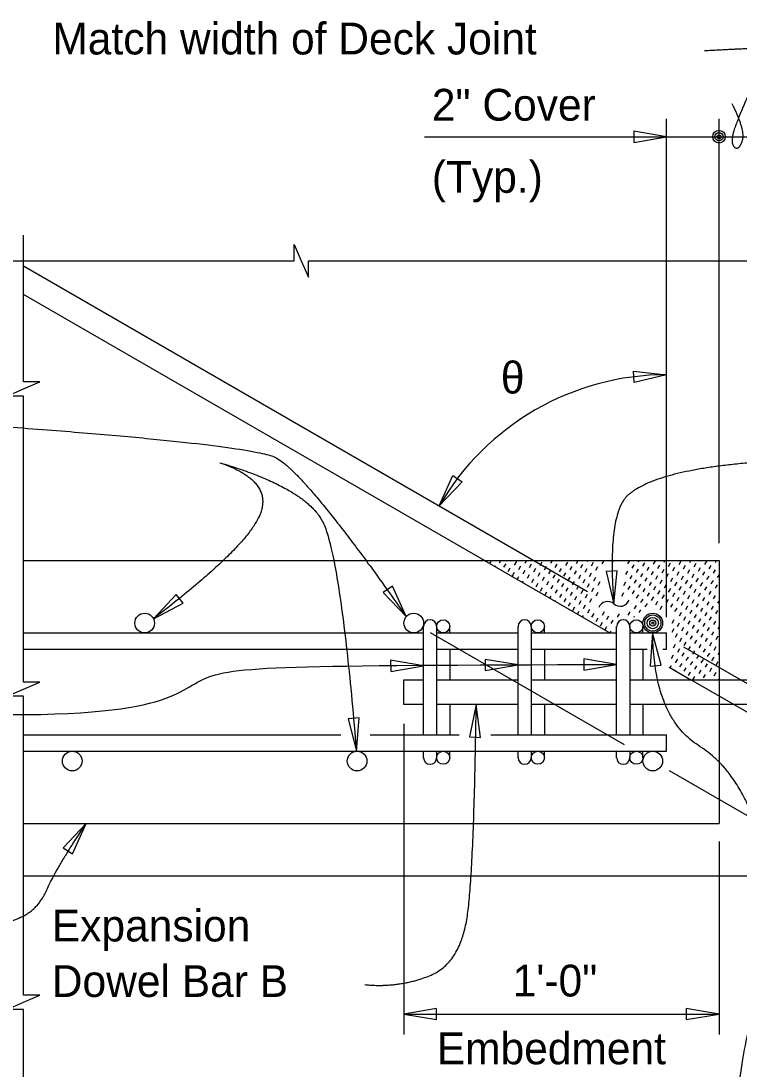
# Model space of a CAD drawing. Extents: x 0 to 20.5, y 0 to 13.
# Drawn here: x 3.293 to 5.57, y 2.072 to 5.395 of the extents above; entities that cross this region are included whole.
import ezdxf

# ---------------------------------------------------------------- set-up
doc = ezdxf.new("R2010")
doc.units = 0
for name, color, linetype in [('Dimension', 7, 'Continuous'), ('Miscellaneous', 7, 'Continuous'), ('Rebar', 7, 'Continuous'), ('TextStructures', 7, 'Continuous'), ('TrafBarrierConc', 7, 'Continuous')]:
    doc.layers.add(name, color=color, linetype=linetype)

msp = doc.modelspace()

# ---------------------------------------------------------------- linework, layer by layer
at = {"layer": 'Dimension'}
for p, q in [((5.3402, 3.5042), (5.3402, 5.0841)), ((5.5069, 3.7386), (5.5069, 5.0841)), ((4.5726, 5.0275), (6.6325, 5.0275)), ((4.5904, 3.456), (5.2064, 3.1004)), ((4.507, 3.1659), (4.507, 2.1806)), ((5.3491, 3.018), (6.7489, 2.2099)), ((5.5069, 2.7927), (5.5069, 2.1806)), ((4.507, 2.2457), (5.5069, 2.2457))]:
    msp.add_line(p, q, dxfattribs=at)
for points in [[(5.3402, 5.0275), (5.2361, 5.0452), (5.2361, 5.0099)], [(5.2352, 4.2842), (5.3402, 4.2732), (5.2375, 4.249)], [(4.6922, 3.9338), (4.6196, 3.8571), (4.6629, 3.9535)], [(5.1731, 3.5466), (5.184, 3.6517), (5.1488, 3.6494)], [(4.5151, 3.506), (4.4714, 3.6022), (4.4422, 3.5824)], [(3.7135, 3.4995), (3.8071, 3.5486), (3.7857, 3.5767)], [(5.2962, 3.4545), (5.2886, 3.3491), (5.3237, 3.3525)], [(4.5697, 3.3505), (4.4655, 3.3677), (4.4657, 3.3325)], [(4.8696, 3.3531), (4.7654, 3.3703), (4.7656, 3.335)], [(5.1821, 3.3548), (5.0779, 3.372), (5.0781, 3.3367)], [(4.7368, 3.2279), (4.715, 3.1245), (4.7503, 3.1231)], [(4.3568, 3.0795), (4.3658, 3.1848), (4.3307, 3.1819)], [(3.4996, 2.8503), (3.4275, 2.7731), (3.457, 2.7537)], [(4.507, 2.2457), (4.6111, 2.2281), (4.6111, 2.2634)], [(5.5069, 2.2457), (5.4028, 2.2634), (5.4028, 2.2281)]]:
    msp.add_lwpolyline(points, close=True, dxfattribs=at)
for points in [[(3.2111, 4.6346), (4.1595, 4.6346), (4.1595, 4.6863), (4.182, 4.6346), (4.2045, 4.583), (4.2045, 4.6346), (5.6705, 4.6346)], [(3.3015, 3.7833), (3.3015, 4.2056), (3.2499, 4.2056), (3.3015, 4.2281), (3.3532, 4.2506), (3.3015, 4.2506), (3.3015, 4.7161)], [(3.3015, 2.5222), (3.3015, 3.2538), (3.2499, 3.2538), (3.3015, 3.2763), (3.3532, 3.2988), (3.3015, 3.2988), (3.3015, 3.7833)], [(3.3015, 1.1553), (3.3015, 2.2607), (3.2499, 2.2607), (3.3015, 2.2832), (3.3532, 2.3057), (3.3015, 2.3057), (3.3015, 2.5222)]]:
    msp.add_lwpolyline(points, dxfattribs=at)
for radius in [0.0199, 0.0131, 0.00592]:
    msp.add_circle((5.5067, 5.0278), radius, dxfattribs=at)
for centre, radius, start, end in [((5.3402, 3.4411), 0.8321, 90, 150.0024), ((5.1934, 3.5687), 0.0298, 227.8396, 339.5668), ((5.1534, 3.5245), 0.0298, 47.8396, 159.5668)]:
    msp.add_arc(centre, radius, start, end, dxfattribs=at)
for points, degree in [([(5.4604, 5.301), (5.5667, 5.3067), (5.6696, 5.3108), (5.5594, 5.0732), (5.5432, 5.0015), (5.5714, 4.9852), (5.5909, 5.0482), (5.5486, 5.1318)], 2), ([(2.9729, 4.1274), (4.0086, 4.0579), (4.195, 3.962), (4.5151, 3.506)], 2), ([(3.9235, 3.9942), (4.0937, 3.9366), (4.0091, 3.7247), (3.7135, 3.4995)], 2), ([(3.9235, 3.9942), (4.1911, 3.9157), (4.3056, 3.7037), (4.3568, 3.0795)], 2), ([(6.0258, 4.0142), (5.6594, 4.0068), (5.2857, 3.9502), (5.1513, 3.8332), (5.173, 3.5466)], 2), ([(5.6346, 2.3146), (5.7045, 2.5366), (5.5862, 3.0064), (5.2999, 3.1865), (5.2963, 3.4545)], 2), ([(3.0126, 3.2007), (3.7468, 3.1725), (3.8032, 3.3526), (4.1263, 3.3505), (5.1821, 3.3548)], 3), ([(4.3833, 2.3391), (4.4944, 2.3283), (4.6907, 2.4097), (4.7303, 2.7298), (4.7368, 3.2279)], 2), ([(5.2452, 1.4729), (5.5852, 1.5133), (5.5498, 1.8019), (5.596, 2.2664), (5.8349, 3.0174)], 2), ([(3.0522, 2.528), (3.1574, 2.528), (3.2363, 2.528), (3.3481, 2.5773), (3.402, 2.7023), (3.4996, 2.8503)], 2)]:
    msp.add_open_spline(points, degree=degree, dxfattribs=at)
at = {"layer": 'Miscellaneous'}
for p, q in [((4.7798, 3.6743), (4.7838, 3.6812)), ((4.796, 3.665), (4.7975, 3.6675)), ((4.8111, 3.6765), (4.8153, 3.6836)), ((4.8248, 3.6628), (4.8313, 3.674)), ((4.8384, 3.6491), (4.8449, 3.6603)), ((4.8449, 3.6829), (4.8453, 3.6836)), ((4.8586, 3.6693), (4.8651, 3.6805)), ((4.8723, 3.6556), (4.8787, 3.6668)), ((4.8924, 3.6758), (4.897, 3.6836)), ((4.9061, 3.6621), (4.9125, 3.6733)), ((4.9197, 3.6484), (4.9262, 3.6596)), ((4.9262, 3.6822), (4.927, 3.6836)), ((4.9399, 3.6686), (4.9464, 3.6798)), ((4.9535, 3.6549), (4.96, 3.6661)), ((4.9737, 3.6751), (4.9786, 3.6836)), ((4.9873, 3.6614), (4.9938, 3.6726)), ((5.001, 3.6477), (5.0075, 3.6589)), ((5.0075, 3.6815), (5.0087, 3.6836)), ((5.0212, 3.6679), (5.0276, 3.6791)), ((5.0348, 3.6542), (5.0413, 3.6654)), ((5.055, 3.6744), (5.0603, 3.6836)), ((5.0686, 3.6607), (5.0751, 3.6719)), ((5.0823, 3.647), (5.0888, 3.6582)), ((5.0888, 3.6808), (5.0904, 3.6836)), ((5.1024, 3.6672), (5.1089, 3.6784)), ((5.1161, 3.6535), (5.1226, 3.6647)), ((5.1362, 3.6737), (5.142, 3.6836)), ((5.17, 3.6801), (5.1721, 3.6836)), ((5.2175, 3.673), (5.2237, 3.6836)), ((5.2312, 3.6593), (5.2377, 3.6705)), ((5.2448, 3.6456), (5.2513, 3.6568)), ((5.2513, 3.6794), (5.2538, 3.6836)), ((5.265, 3.6658), (5.2715, 3.677)), ((5.2787, 3.6521), (5.2851, 3.6633)), ((5.2988, 3.6723), (5.3053, 3.6835)), ((5.3125, 3.6586), (5.3189, 3.6698)), ((5.3261, 3.6449), (5.3326, 3.6561)), ((5.3326, 3.6787), (5.3354, 3.6836)), ((5.3463, 3.6651), (5.3528, 3.6763)), ((5.3599, 3.6514), (5.3664, 3.6626)), ((5.3801, 3.6716), (5.3866, 3.6828)), ((5.3937, 3.6579), (5.4002, 3.6691)), ((5.4139, 3.678), (5.4171, 3.6836)), ((5.4276, 3.6644), (5.434, 3.6756)), ((5.4412, 3.6507), (5.4477, 3.6619)), ((5.4614, 3.6709), (5.4678, 3.6821)), ((5.475, 3.6572), (5.4815, 3.6684)), ((5.4952, 3.6773), (5.4988, 3.6836)), ((4.8521, 3.6355), (4.8586, 3.6467)), ((4.867, 3.624), (4.8723, 3.633)), ((4.8859, 3.642), (4.8924, 3.6531)), ((4.8996, 3.6283), (4.9061, 3.6395)), ((4.9132, 3.6146), (4.9197, 3.6258)), ((4.9334, 3.6348), (4.9399, 3.646)), ((4.9471, 3.6211), (4.9535, 3.6323)), ((4.9672, 3.6413), (4.9737, 3.6524)), ((4.9809, 3.6276), (4.9873, 3.6388)), ((4.9945, 3.6139), (5.001, 3.6251)), ((5.0147, 3.6341), (5.0212, 3.6453)), ((5.0283, 3.6204), (5.0348, 3.6316)), ((5.0485, 3.6406), (5.055, 3.6517)), ((5.0621, 3.6269), (5.0686, 3.6381)), ((5.0758, 3.6132), (5.0823, 3.6244)), ((5.0959, 3.6334), (5.1024, 3.6446)), ((5.1096, 3.6197), (5.1161, 3.6309)), ((5.211, 3.6392), (5.2175, 3.6503)), ((5.2247, 3.6255), (5.2312, 3.6367)), ((5.2384, 3.6118), (5.2448, 3.623)), ((5.2585, 3.632), (5.265, 3.6432)), ((5.2722, 3.6183), (5.2787, 3.6295)), ((5.2923, 3.6385), (5.2988, 3.6496)), ((5.306, 3.6248), (5.3125, 3.636)), ((5.3398, 3.6313), (5.3463, 3.6425)), ((5.3535, 3.6176), (5.3599, 3.6288)), ((5.3736, 3.6378), (5.3801, 3.6489)), ((5.3873, 3.6241), (5.3937, 3.6353)), ((5.4074, 3.6442), (5.4139, 3.6554)), ((5.4211, 3.6306), (5.4276, 3.6418)), ((5.4347, 3.6169), (5.4412, 3.6281)), ((5.4549, 3.6371), (5.4614, 3.6482)), ((5.4685, 3.6234), (5.475, 3.6346)), ((5.4887, 3.6435), (5.4952, 3.6547)), ((5.5024, 3.6299), (5.5069, 3.6377)), ((4.8832, 3.6146), (4.8859, 3.6193)), ((4.8994, 3.6053), (4.8996, 3.6057)), ((4.9269, 3.601), (4.9334, 3.6122)), ((4.9406, 3.5873), (4.9471, 3.5985)), ((4.9607, 3.6074), (4.9672, 3.6186)), ((4.9744, 3.5938), (4.9809, 3.605)), ((4.988, 3.5801), (4.9945, 3.5913)), ((5.0082, 3.6003), (5.0147, 3.6115)), ((5.0219, 3.5866), (5.0283, 3.5978)), ((5.042, 3.6067), (5.0485, 3.6179)), ((5.0557, 3.5931), (5.0621, 3.6043)), ((5.0693, 3.5794), (5.0758, 3.5906)), ((5.0895, 3.5996), (5.0959, 3.6108)), ((5.1031, 3.5859), (5.1096, 3.5971)), ((5.1233, 3.606), (5.1298, 3.6172)), ((5.2046, 3.6053), (5.211, 3.6165)), ((5.2182, 3.5917), (5.2247, 3.6029)), ((5.252, 3.5982), (5.2585, 3.6094)), ((5.2657, 3.5845), (5.2722, 3.5957)), ((5.2858, 3.6046), (5.2923, 3.6158)), ((5.2995, 3.591), (5.306, 3.6022)), ((5.3196, 3.6111), (5.3261, 3.6223)), ((5.3333, 3.5975), (5.3398, 3.6087)), ((5.347, 3.5838), (5.3535, 3.595)), ((5.3671, 3.6039), (5.3736, 3.6151)), ((5.3808, 3.5903), (5.3873, 3.6015)), ((5.4009, 3.6104), (5.4074, 3.6216)), ((5.4146, 3.5968), (5.4211, 3.608)), ((5.4283, 3.5831), (5.4347, 3.5943)), ((5.4484, 3.6032), (5.4549, 3.6144)), ((5.4621, 3.5896), (5.4685, 3.6008)), ((5.4822, 3.6097), (5.4887, 3.6209)), ((5.4959, 3.5961), (5.5024, 3.6073)), ((4.9542, 3.5736), (4.9607, 3.5848)), ((4.9704, 3.5643), (4.9744, 3.5712)), ((4.9866, 3.555), (4.988, 3.5575)), ((5.0017, 3.5665), (5.0082, 3.5776)), ((5.0154, 3.5528), (5.0219, 3.564)), ((5.0355, 3.5729), (5.042, 3.5841)), ((5.0492, 3.5593), (5.0557, 3.5705)), ((5.0628, 3.5456), (5.0693, 3.5568)), ((5.083, 3.5658), (5.0895, 3.5769)), ((5.0966, 3.5521), (5.1031, 3.5633)), ((5.1168, 3.5722), (5.1233, 3.5834)), ((5.1981, 3.5715), (5.2046, 3.5827)), ((5.2319, 3.578), (5.2384, 3.5892)), ((5.2455, 3.5644), (5.252, 3.5755)), ((5.2592, 3.5507), (5.2657, 3.5619)), ((5.2794, 3.5708), (5.2858, 3.582)), ((5.293, 3.5572), (5.2995, 3.5684)), ((5.3132, 3.5773), (5.3196, 3.5885)), ((5.3268, 3.5637), (5.3333, 3.5748)), ((5.3405, 3.55), (5.347, 3.5612)), ((5.3606, 3.5701), (5.3671, 3.5813)), ((5.3743, 3.5565), (5.3808, 3.5677)), ((5.3944, 3.5766), (5.4009, 3.5878)), ((5.4081, 3.563), (5.4146, 3.5741)), ((5.4218, 3.5493), (5.4283, 3.5605)), ((5.4419, 3.5694), (5.4484, 3.5806)), ((5.4556, 3.5558), (5.4621, 3.567)), ((5.4757, 3.5759), (5.4822, 3.5871)), ((5.4894, 3.5623), (5.4959, 3.5734)), ((5.029, 3.5391), (5.0355, 3.5503)), ((5.0427, 3.5255), (5.0492, 3.5367)), ((5.0576, 3.5139), (5.0628, 3.523)), ((5.0765, 3.5319), (5.083, 3.5431)), ((5.0902, 3.5183), (5.0966, 3.5295)), ((5.2391, 3.5305), (5.2455, 3.5417)), ((5.2539, 3.519), (5.2592, 3.5281)), ((5.2729, 3.537), (5.2794, 3.5482)), ((5.3067, 3.5435), (5.3132, 3.5547)), ((5.3196, 3.5292), (5.3261, 3.5404)), ((5.3534, 3.5357), (5.3599, 3.5469)), ((5.3671, 3.5221), (5.3735, 3.5332)), ((5.388, 3.5428), (5.3944, 3.554)), ((5.4016, 3.5291), (5.4081, 3.5403)), ((5.4153, 3.5155), (5.4218, 3.5267)), ((5.4354, 3.5356), (5.4419, 3.5468)), ((5.4491, 3.522), (5.4556, 3.5332)), ((5.4692, 3.5421), (5.4757, 3.5533)), ((5.4829, 3.5284), (5.4894, 3.5396)), ((5.4966, 3.5148), (5.5031, 3.526)), ((5.5031, 3.5486), (5.5069, 3.5553)), ((5.0738, 3.5046), (5.0765, 3.5093)), ((5.0899, 3.4953), (5.0902, 3.4957)), ((5.1038, 3.5046), (5.1103, 3.5158)), ((5.1175, 3.491), (5.124, 3.5021)), ((5.1376, 3.5111), (5.1441, 3.5223)), ((5.1513, 3.4974), (5.1578, 3.5086)), ((5.165, 3.4838), (5.1714, 3.495)), ((5.1851, 3.5039), (5.1916, 3.5151)), ((5.2189, 3.5104), (5.2254, 3.5216)), ((5.2372, 3.5047), (5.2391, 3.5079)), ((5.358, 3.4856), (5.3645, 3.4968)), ((5.3815, 3.509), (5.388, 3.5202)), ((5.3951, 3.4953), (5.4016, 3.5065)), ((5.4088, 3.4817), (5.4153, 3.4929)), ((5.429, 3.5018), (5.4354, 3.513)), ((5.4426, 3.4882), (5.4491, 3.4994)), ((5.4628, 3.5083), (5.4692, 3.5195)), ((5.4764, 3.4946), (5.4829, 3.5058)), ((5.4901, 3.481), (5.4966, 3.4922)), ((5.1312, 3.4773), (5.1376, 3.4885)), ((5.1448, 3.4636), (5.1513, 3.4748)), ((5.1611, 3.4545), (5.165, 3.4612)), ((5.358, 3.4568), (5.3645, 3.468)), ((5.375, 3.4752), (5.3815, 3.4864)), ((5.3887, 3.4615), (5.3951, 3.4727)), ((5.4023, 3.4479), (5.4088, 3.4591)), ((5.4225, 3.468), (5.429, 3.4792)), ((5.4361, 3.4543), (5.4426, 3.4655)), ((5.4563, 3.4745), (5.4628, 3.4857)), ((5.4699, 3.4608), (5.4764, 3.472)), ((5.4836, 3.4472), (5.4901, 3.4584)), ((5.5038, 3.4673), (5.5069, 3.4728)), ((5.3685, 3.4414), (5.375, 3.4526)), ((5.3822, 3.4277), (5.3887, 3.4389)), ((5.3958, 3.4141), (5.4023, 3.4253)), ((5.416, 3.4342), (5.4225, 3.4454)), ((5.4297, 3.4205), (5.4361, 3.4317)), ((5.4498, 3.4407), (5.4563, 3.4519)), ((5.4635, 3.427), (5.4699, 3.4382)), ((5.4771, 3.4134), (5.4836, 3.4246)), ((5.4973, 3.4335), (5.5038, 3.4447)), ((5.362, 3.4076), (5.3685, 3.4188)), ((5.3757, 3.3939), (5.3822, 3.4051)), ((5.3894, 3.3802), (5.3958, 3.3914)), ((5.4095, 3.4004), (5.416, 3.4116)), ((5.4232, 3.3867), (5.4297, 3.3979)), ((5.4433, 3.4069), (5.4498, 3.4181)), ((5.457, 3.3932), (5.4635, 3.4044)), ((5.4706, 3.3795), (5.4771, 3.3907)), ((5.4908, 3.3997), (5.4973, 3.4109)), ((5.5045, 3.386), (5.5069, 3.3903)), ((5.3556, 3.3738), (5.362, 3.385)), ((5.3692, 3.3601), (5.3757, 3.3713)), ((5.3829, 3.3464), (5.3894, 3.3576)), ((5.403, 3.3666), (5.4095, 3.3778)), ((5.4167, 3.3529), (5.4232, 3.3641)), ((5.4368, 3.3731), (5.4433, 3.3843)), ((5.4505, 3.3594), (5.457, 3.3706)), ((5.4642, 3.3457), (5.4706, 3.3569)), ((5.4843, 3.3659), (5.4908, 3.3771)), ((5.498, 3.3522), (5.5045, 3.3634)), ((5.3516, 3.3442), (5.3556, 3.3512)), ((5.3677, 3.3349), (5.3692, 3.3375)), ((5.3965, 3.3328), (5.403, 3.344)), ((5.4102, 3.3191), (5.4167, 3.3303)), ((5.4304, 3.3393), (5.4368, 3.3505)), ((5.444, 3.3256), (5.4505, 3.3368)), ((5.4778, 3.3321), (5.4843, 3.3433)), ((5.4915, 3.3184), (5.498, 3.3296)), ((5.4239, 3.3054), (5.4304, 3.3166)), ((5.4577, 3.3119), (5.4642, 3.3231)), ((5.5052, 3.3047), (5.5069, 3.3078))]:
    msp.add_line(p, q, dxfattribs=at)
for points in [[(4.7636, 3.6836), (5.1606, 3.4545)], [(5.3488, 3.3458), (5.4178, 3.306)]]:
    msp.add_lwpolyline(points, dxfattribs=at)
at = {"layer": 'Rebar'}
for p, q in [((4.5698, 3.1316), (4.5698, 3.4753)), ((4.6114, 3.4753), (4.6114, 3.1316)), ((4.6531, 3.4545), (4.6531, 3.4753)), ((4.8696, 3.1316), (4.8696, 3.4753)), ((4.9113, 3.4753), (4.9113, 3.1316)), ((4.953, 3.4545), (4.953, 3.4753)), ((5.1821, 3.1316), (5.1821, 3.4753)), ((5.2238, 3.4753), (5.2238, 3.4157)), ((5.2655, 3.4545), (5.2655, 3.4753)), ((3.3015, 3.4545), (4.5697, 3.4545)), ((4.6114, 3.4545), (4.8696, 3.4545)), ((4.9113, 3.4545), (5.1821, 3.4545)), ((5.2238, 3.4545), (5.2967, 3.4545)), ((5.2963, 3.4545), (5.3402, 3.4545)), ((5.3402, 3.4024), (5.3402, 3.4545)), ((3.3015, 3.4024), (4.5697, 3.4024)), ((4.6114, 3.4024), (4.8696, 3.4024)), ((4.6531, 3.4024), (4.6531, 3.3061)), ((4.9113, 3.4024), (5.1821, 3.4024)), ((4.953, 3.4024), (4.953, 3.3061)), ((5.2238, 3.4157), (5.2238, 3.1316)), ((5.2238, 3.4024), (5.2786, 3.4024)), ((5.2655, 3.4024), (5.2655, 3.3061)), ((5.329, 3.4024), (5.3402, 3.4024)), ((4.6531, 3.2279), (4.6531, 3.1316)), ((4.953, 3.2279), (4.953, 3.1316)), ((5.2655, 3.2279), (5.2655, 3.1316)), ((3.3015, 3.1316), (4.3075, 3.1316)), ((4.4009, 3.1316), (4.6832, 3.1316)), ((4.7831, 3.1316), (5.3402, 3.1316)), ((5.3402, 3.0795), (5.3402, 3.1316)), ((3.3015, 3.0795), (5.3402, 3.0795)), ((4.5698, 3.0587), (4.5698, 3.0795)), ((4.6114, 3.0795), (4.6114, 3.0587)), ((4.6531, 3.0587), (4.6531, 3.0795)), ((4.8696, 3.0587), (4.8696, 3.0795)), ((4.9113, 3.0795), (4.9113, 3.0587)), ((4.953, 3.0587), (4.953, 3.0795)), ((5.1821, 3.0587), (5.1821, 3.0795)), ((5.2238, 3.0795), (5.2238, 3.0587)), ((5.2655, 3.0587), (5.2655, 3.0795))]:
    msp.add_line(p, q, dxfattribs=at)
for points in [[(4.5698, 3.2279), (4.507, 3.2279), (4.507, 3.306), (4.5698, 3.306)], [(4.6114, 3.306), (4.8696, 3.306)], [(4.9113, 3.306), (5.1821, 3.306)], [(5.2238, 3.306), (5.8709, 3.306)], [(4.8696, 3.2279), (4.6114, 3.2279)], [(5.1821, 3.2279), (4.9113, 3.2279)], [(5.8709, 3.2279), (5.2238, 3.2279)]]:
    msp.add_lwpolyline(points, dxfattribs=at)
for centre, radius in [((3.6855, 3.4857), 0.0312), ((4.5389, 3.4857), 0.0312), ((4.6323, 3.4753), 0.0208), ((4.9321, 3.4753), 0.0208), ((5.2446, 3.4753), 0.0208), ((5.2967, 3.4857), 0.0312), ((5.2967, 3.4857), 0.0257), ((5.2967, 3.4857), 0.0178), ((5.2967, 3.4857), 0.00969), ((5.2967, 3.4857), 0.00342), ((3.4559, 3.0482), 0.0312), ((4.3592, 3.0482), 0.0312), ((4.6323, 3.0587), 0.0208), ((4.9321, 3.0587), 0.0208), ((5.2446, 3.0587), 0.0208), ((5.2967, 3.0482), 0.0312)]:
    msp.add_circle(centre, radius, dxfattribs=at)
for centre, start, end in [((4.5906, 3.4753), 0, 180), ((4.8905, 3.4753), 0, 180), ((5.203, 3.4753), 0, 180), ((4.5906, 3.0587), 180, 0), ((4.8905, 3.0587), 180, 0), ((5.203, 3.0587), 180, 0)]:
    msp.add_arc(centre, 0.0208, start, end, dxfattribs=at)
at = {"layer": 'TrafBarrierConc'}
for p, q in [((3.3015, 4.618), (5.0897, 3.5857)), ((4.7636, 3.6836), (3.3015, 4.5277)), ((3.3015, 3.6836), (5.5069, 3.6836)), ((5.507, 3.6836), (5.507, 2.8503)), ((5.3936, 3.4103), (5.7516, 3.2036)), ((5.6651, 3.1632), (5.4178, 3.306)), ((3.3015, 2.8503), (5.5069, 2.8503)), ((6.4959, 2.6836), (3.3015, 2.6836))]:
    msp.add_line(p, q, dxfattribs=at)

# ---------------------------------------------------------------- texts
at = {"layer": 'Dimension'}
for s, p in [('2" Cover', (4.5961, 5.0788)), ('(Typ.)', (4.5961, 4.85)), ('Expansion ', (3.3911, 2.4761)), ('Dowel Bar B ', (3.3911, 2.3001))]:
    msp.add_text(s, height=0.1008, dxfattribs=at).set_placement(p)
at = {"layer": 'TextStructures'}
for s, p in [('Match width of Deck Joint', (3.393, 5.2887)), ('θ', (4.8149, 4.2135)), ('1\'-0"', (4.8523, 2.3016)), ('Embedment', (4.6117, 2.0867))]:
    msp.add_text(s, height=0.1008, dxfattribs=at).set_placement(p)

doc.saveas('drawing.dxf')
